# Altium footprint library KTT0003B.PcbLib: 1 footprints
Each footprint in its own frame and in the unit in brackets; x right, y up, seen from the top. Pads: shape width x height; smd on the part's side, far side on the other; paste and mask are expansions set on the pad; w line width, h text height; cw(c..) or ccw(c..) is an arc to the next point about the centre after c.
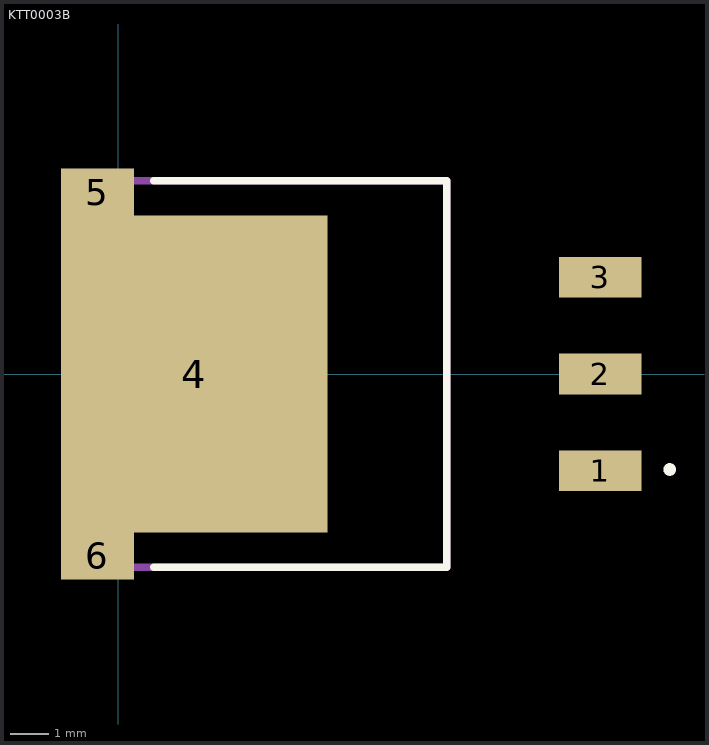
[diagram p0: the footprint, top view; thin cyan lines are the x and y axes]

## KTT0003B [mm]
pads (6):
  rect 2.16x1.07 smd: 1(12.67,-2.54) 2(12.67,0) 3(12.67,2.54)
  rect 7x8.33 smd: 4(2,0)
  rect 1.91x1.235 smd: 5(-0.545,4.782) 6(-0.545,-4.782)
Top Overlay:
  circle w0.2: c14.497,-2.51 r0.065
  lines w0.2: 0.94,-5.08 8.64,-5.08 8.64,5.08 0.94,5.08
Mechanical 15:
  lines w0.2: 0,-5.08 8.64,-5.08 8.64,5.08 0,5.08 0,-5.08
